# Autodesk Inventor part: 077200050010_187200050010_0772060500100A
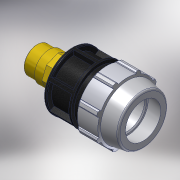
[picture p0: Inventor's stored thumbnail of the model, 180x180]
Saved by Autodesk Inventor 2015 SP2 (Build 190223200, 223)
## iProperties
Created: 2017-02
Part Number: 077200050010_187200050010_0772060500100A
Material: PVC-Piping
Description: PLASSON MALE ADAPTOR INTEGRAL BRASS THREAD 50-1"
Document SubType Name: Modeling
Designer: KIM
Mass: 92.6774 g
Surface Area: 199.44 cm^2
Volume: 66.1981 cm^3
Density: 1.4 g/cm^3
Appearance: PTFE
Author: KIM
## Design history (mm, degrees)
derived "07720.ipt"
feature "Solid1::07720.ipt"
tag "TaggingFeature1"
body "Solid1"
other parameters: "d4" = 24.14286, "d5" = 24.14286, "d7" = 96, "d8" = 72, "d9" = 24.14286, "d11" = 4.82857, "d12" = 76.8, "d13" = 120 deg, "d14" = 75, "d15" = 10 deg, "d16" = 86.4, "d18" = 2.5, "d19" = 35 deg, "d20" = 17.5 deg, "d21" = 89.28, "d23" = 0, "d25" = 360 deg, "d27" = 1.92, "d34" = 4.8, "d36" = 0, "d42" = 33.8, "d43" = 2.88, "d46" = 1.5, "d49" = 106, "d51" = 169, "d53" = 1, "d55" = 360 deg, "d59" = 33.8, "d60" = 33.249, "d61" = 36.5739, "d63" = 56.33333, "d64" = 23.2743, "d65" = 169, "d66" = 20.64822, "d67" = 0, "d68" = 1, "d71" = 30 deg, "d72" = 29.9241, "E_" = 96, "H_" = 169, "l_" = 106, "R_" = 33.249, "d73" = 34.4137
